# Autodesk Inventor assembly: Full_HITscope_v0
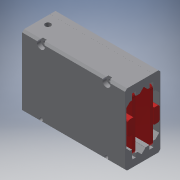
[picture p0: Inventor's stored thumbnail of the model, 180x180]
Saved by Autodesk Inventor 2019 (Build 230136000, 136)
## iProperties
Created: 2021-09
Part Number: Full_HITscope_v0
Material: Generisch
Document SubType Name: Assembly
Designer: Muriel
Author: Muriel
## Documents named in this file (2)
- C:\Users\Muriel\Documents\Inventor\HITscope\Full_HITscope_v0.iam
- C:\Users\Muriel\Documents\Inventor\HITscope\Assembly_HITscope.iam
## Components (1 placed, 1 different names)
1. Assembly_HITscope:1 [sub-assembly]
